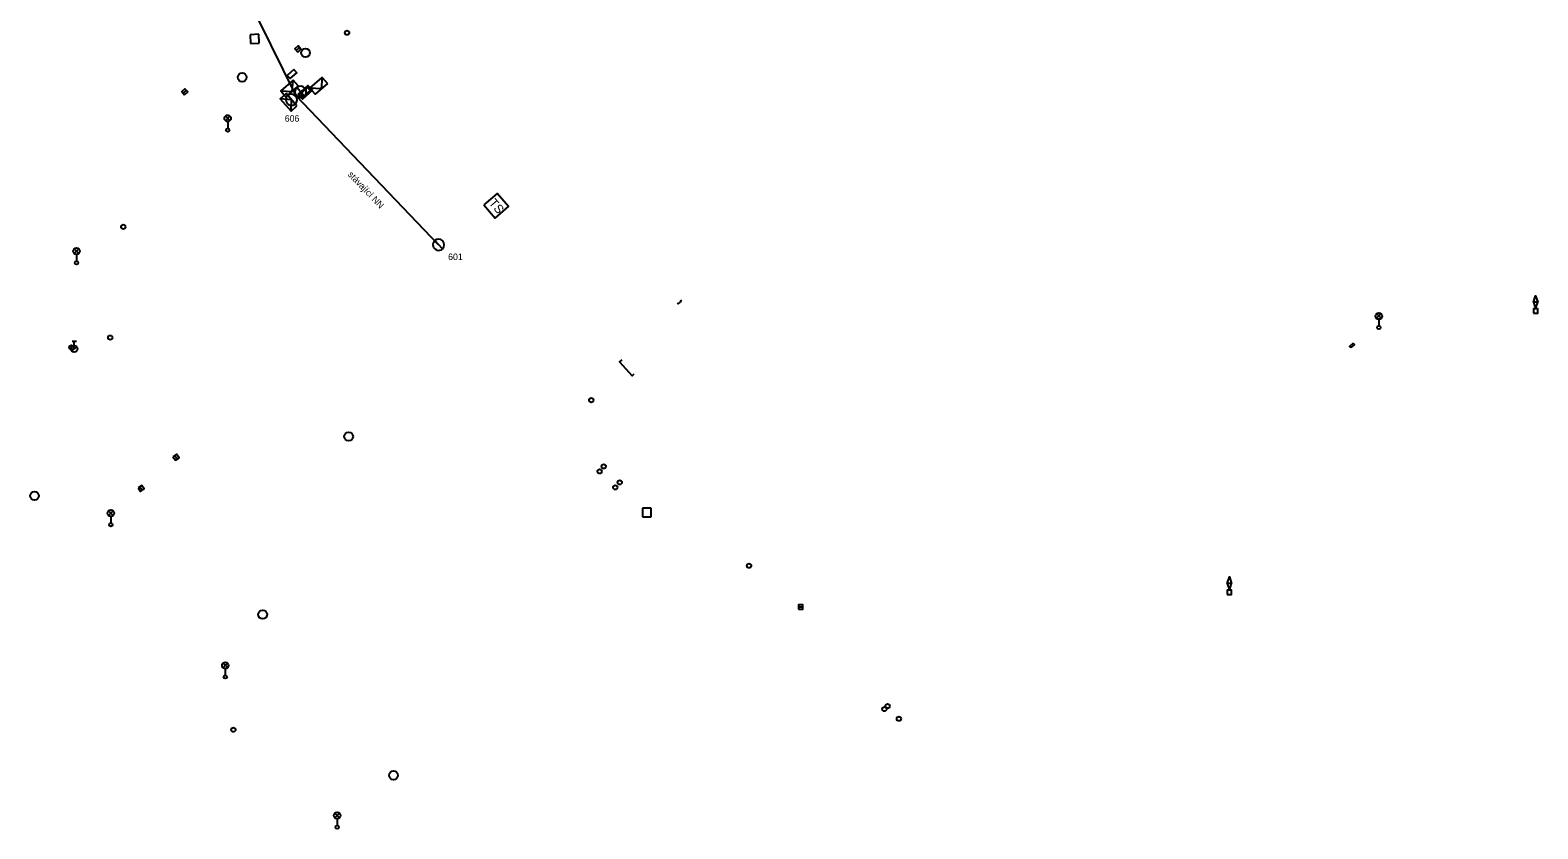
# Model space of a CAD drawing. Extents: x -584388 to -581645, y -1210859 to -1208922.
# Drawn here: x -582436.8 to -582264.1, y -1209795 to -1209703.5 of the extents above; entities that cross this region are included whole.
import ezdxf

# ---------------------------------------------------------------- set-up
doc = ezdxf.new("R2010")
doc.units = 0
for name, color, linetype in [('CIZÍ_NADZEM', 7, 'Continuous'), ('ELE_EON', 7, 'Continuous'), ('ELE_EON_POPIS', 7, 'Continuous')]:
    doc.layers.add(name, color=color, linetype=linetype)

msp = doc.modelspace()

# ---------------------------------------------------------------- linework, layer by layer
at = {"layer": 'CIZÍ_NADZEM'}
for p, q in [((-582410.6, -1209703.99), (-582411.6, -1209704.05)), ((-582411.6, -1209704.05), (-582411.54, -1209705.05)), ((-582411.54, -1209705.05), (-582410.54, -1209704.99)), ((-582410.54, -1209704.99), (-582410.6, -1209703.99)), ((-582406.31, -1209705.83), (-582405.93, -1209705.51)), ((-582419.26, -1209710.74), (-582418.88, -1209710.42)), ((-582414.42, -1209713.89), (-582413.9, -1209713.36)), ((-582413.89, -1209713.89), (-582414.42, -1209713.36)), ((-582414.16, -1209714), (-582414.16, -1209714.75)), ((-582431.74, -1209729.11), (-582431.22, -1209728.58)), ((-582431.21, -1209729.1), (-582431.74, -1209728.58)), ((-582431.48, -1209729.22), (-582431.48, -1209729.97)), ((-582282.53, -1209736.53), (-582282.01, -1209736)), ((-582282, -1209736.53), (-582282.53, -1209736)), ((-582282.27, -1209736.64), (-582282.27, -1209737.39)), ((-582431.99, -1209739.15), (-582431.49, -1209739.15)), ((-582431.74, -1209739.65), (-582431.74, -1209739.15)), ((-582432.03, -1209740.25), (-582431.44, -1209739.79)), ((-582420.22, -1209752.25), (-582419.94, -1209752.65)), ((-582424.21, -1209755.83), (-582423.93, -1209756.23)), ((-582427.81, -1209759.12), (-582427.29, -1209758.59)), ((-582427.28, -1209759.11), (-582427.81, -1209758.59)), ((-582365.62, -1209758.27), (-582366.62, -1209758.27)), ((-582366.62, -1209758.27), (-582366.62, -1209759.27)), ((-582365.62, -1209759.27), (-582365.62, -1209758.27)), ((-582427.55, -1209759.23), (-582427.55, -1209759.98)), ((-582366.62, -1209759.27), (-582365.62, -1209759.27)), ((-582348.77, -1209769.61), (-582348.27, -1209769.61)), ((-582414.69, -1209776.56), (-582414.17, -1209776.03)), ((-582414.16, -1209776.56), (-582414.69, -1209776.03)), ((-582414.43, -1209776.67), (-582414.43, -1209777.42)), ((-582401.87, -1209793.77), (-582401.35, -1209793.24)), ((-582401.34, -1209793.77), (-582401.87, -1209793.24)), ((-582401.61, -1209793.88), (-582401.61, -1209794.63))]:
    msp.add_line(p, q, dxfattribs=at)
for points in [[(-582406.14, -1209706.02), (-582405.77, -1209705.69), (-582406.1, -1209705.32), (-582406.47, -1209705.65)], [(-582406.59, -1209708.03), (-582407.33, -1209708.7), (-582406.99, -1209709.07), (-582406.25, -1209708.4)], [(-582419.09, -1209710.93), (-582418.72, -1209710.6), (-582419.05, -1209710.23), (-582419.42, -1209710.56)], [(-582264.55, -1209735.95), (-582264.05, -1209735.95), (-582264.05, -1209735.45), (-582264.55, -1209735.45)], [(-582420.43, -1209752.39), (-582420.14, -1209752.8), (-582419.73, -1209752.51), (-582420.02, -1209752.1)], [(-582424.42, -1209755.97), (-582424.13, -1209756.38), (-582423.72, -1209756.09), (-582424.01, -1209755.68)], [(-582299.64, -1209768.17), (-582299.14, -1209768.17), (-582299.14, -1209767.67), (-582299.64, -1209767.67)], [(-582348.77, -1209769.86), (-582348.27, -1209769.86), (-582348.27, -1209769.36), (-582348.77, -1209769.36)]]:
    msp.add_lwpolyline(points, close=True, dxfattribs=at)
for points in [[(-582362.29, -1209734.41), (-582362.16, -1209734.55)], [(-582264.55, -1209734.7), (-582264.3, -1209735.45), (-582264.05, -1209734.7), (-582264.55, -1209734.7), (-582264.3, -1209733.95), (-582264.05, -1209734.7)], [(-582362.66, -1209734.74), (-582362.53, -1209734.88), (-582362.16, -1209734.55)], [(-582285.21, -1209739.38), (-582285.62, -1209739.75), (-582285.48, -1209739.89)], [(-582285.21, -1209739.38), (-582285.07, -1209739.52), (-582285.48, -1209739.89)], [(-582369.01, -1209741.29), (-582369.25, -1209741.51), (-582367.82, -1209743.11), (-582367.58, -1209742.9)], [(-582299.64, -1209766.92), (-582299.39, -1209767.67), (-582299.14, -1209766.92), (-582299.64, -1209766.92), (-582299.39, -1209766.17), (-582299.14, -1209766.92)]]:
    msp.add_lwpolyline(points, dxfattribs=at)
for centre, radius in [((-582400.48, -1209703.82), 0.25), ((-582405.23, -1209706.11), 0.5), ((-582412.5, -1209708.92), 0.5), ((-582414.16, -1209713.62), 0.375), ((-582414.16, -1209714.95), 0.2), ((-582426.12, -1209726.05), 0.25), ((-582431.48, -1209728.84), 0.375), ((-582431.48, -1209730.17), 0.2), ((-582282.27, -1209736.27), 0.375), ((-582282.27, -1209737.59), 0.2), ((-582432.06, -1209739.86), 0.25), ((-582431.74, -1209740.02), 0.375), ((-582427.62, -1209738.74), 0.25), ((-582372.5, -1209745.91), 0.25), ((-582400.3, -1209750.08), 0.5), ((-582371.07, -1209753.51), 0.25), ((-582371.55, -1209754.08), 0.25), ((-582369.24, -1209755.34), 0.25), ((-582436.29, -1209756.87), 0.5), ((-582369.75, -1209755.91), 0.25), ((-582427.55, -1209758.85), 0.375), ((-582427.55, -1209760.18), 0.2), ((-582354.42, -1209764.89), 0.25), ((-582410.15, -1209770.48), 0.5), ((-582414.43, -1209776.3), 0.375), ((-582414.43, -1209777.62), 0.2), ((-582338.92, -1209781.3), 0.25), ((-582338.55, -1209780.97), 0.25), ((-582337.26, -1209782.42), 0.25), ((-582413.5, -1209783.67), 0.25), ((-582395.16, -1209788.9), 0.5), ((-582401.61, -1209793.51), 0.375), ((-582401.61, -1209794.83), 0.2)]:
    msp.add_circle(centre, radius, dxfattribs=at)
at = {"layer": 'ELE_EON'}
for p, q in [((-582405.38, -1209711.07), (-582406.23, -1209710.09)), ((-582406.43, -1209711.99), (-582407.28, -1209711.01)), ((-582389.54, -1209728.57), (-582390.44, -1209727.63))]:
    msp.add_line(p, q, dxfattribs=at)
for points in [[(-582389.99, -1209728.1), (-582406.33, -1209711.04), (-582412.06, -1209699.3)], [(-582408.08, -1209710.47), (-582406.78, -1209710.53), (-582406.67, -1209709.23)], [(-582403.33, -1209708.94), (-582403.43, -1209710.23), (-582404.73, -1209710.18)], [(-582406.9, -1209712.79), (-582406.84, -1209711.49), (-582408.14, -1209711.38)]]:
    msp.add_lwpolyline(points, dxfattribs=at)
for points in [[(-582407.48, -1209711.15), (-582406.08, -1209709.91), (-582406.67, -1209709.23), (-582408.08, -1209710.47)], [(-582404.46, -1209710.41), (-582405.58, -1209711.41), (-582406.08, -1209710.85), (-582404.96, -1209709.85)], [(-582404.71, -1209710.43), (-582405.53, -1209711.16), (-582405.83, -1209710.83), (-582405.01, -1209710.1)], [(-582402.73, -1209709.61), (-582404.13, -1209710.86), (-582404.73, -1209710.18), (-582403.33, -1209708.94)], [(-582406.22, -1209712.19), (-582407.46, -1209710.79), (-582408.14, -1209711.38), (-582406.9, -1209712.79)], [(-582384.8, -1209723.52), (-582383.5, -1209725.04), (-582381.98, -1209723.74), (-582383.28, -1209722.22)]]:
    msp.add_lwpolyline(points, close=True, dxfattribs=at)
for centre, start, end in [((-582405.8, -1209710.58), 131.2686, 311.2686), ((-582405.8, -1209710.58), 311.2686, 131.2686), ((-582406.86, -1209711.5), 131.2686, 311.2686), ((-582406.86, -1209711.5), 311.2686, 131.2686), ((-582389.99, -1209728.1), 313.7651, 133.7651), ((-582389.99, -1209728.1), 133.7651, 313.7651)]:
    msp.add_arc(centre, 0.65, start, end, dxfattribs=at)

# ---------------------------------------------------------------- texts
msp.add_text('TS', height=1, rotation=310.4752, dxfattribs=at).set_placement((-582384.29, -1209723.35))
at = {"layer": 'ELE_EON_POPIS'}
for s, p in [('606', (-582407.62, -1209714.01)), ('601', (-582388.9, -1209729.86))]:
    msp.add_text(s, height=0.75, dxfattribs=at).set_placement(p)
msp.add_text('stávající NN', height=0.75, rotation=313.7651, dxfattribs=at).set_placement((-582400.45, -1209720.11))

doc.saveas('drawing.dxf')
